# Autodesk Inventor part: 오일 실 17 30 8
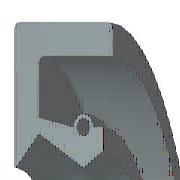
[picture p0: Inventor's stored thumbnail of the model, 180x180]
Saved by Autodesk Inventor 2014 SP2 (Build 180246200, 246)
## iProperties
IsCustomPart: 1
Created: 2012-02
Part Number: 오일 실 17 30 8
Material: 고무
Description: 오일-실
Document SubType Name: Modeling
Standard: KS B 2804
Designer: mduedu
Standards Organization: KS
Language: ko-KR
Size Designation: D - 17 30 8
Categories: <MemberInstance><Categories><Category DisplayName="샤프트 부품" InternalName="7f7aeb1f-a693-4053-b835-cee3144e0d98" Mnemonic="SHFT"><Category DisplayName="실링" Intern
Density: 0.93 g/cm^3
Appearance: 고무 - 검은색 - 버전 1.1
Author: mduedu
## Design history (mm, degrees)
revolve "본체" stored, may be unused: angle "d17" = 90 deg
revolve "스프링1" stored, may be unused: angle "d18" = 90 deg
body "Solid1"
sketch "스케치1"
  geometry: L1 (0, 15)-(8, 15); L2 (8, 13.25)-(1.75, 13.25); L3 (1.75, 10.25)-(4.9, 8.5); L4 (4.9, 8.5)-(0, 8.5); L5 (0, 0)-(9.586, 0) reference; L6 (4.9, 8.5)-(6.3, 9.375); L7 (0, 18)-(0, -3) reference; L8 (-1.941, 0)-(11.507, 0) reference; L9 (4.2, 10.6)-(1.75, 11.21); L10 (1.75, 11.21)-(1.75, 13.25); L11 (0, 15)-(0, 8.588); L12 (4.9, 8.5)-(0, 8.5); L13 (1.75, 10.25)-(0.152, 8.528); L14 (8, 15)-(8, 13.25); L15 (5.6, 10.6)-(6.3, 10.6); L16 (6.3, 10.6)-(6.3, 9.375); C1 r 0.455 at (4.9, 10.6); A1 r 0.7 centre (4.9, 10.6) between (5.6, 10.6) and (4.2, 10.6); A2 r 0.088 centre (0.088, 8.588) between (0, 8.588) and (0.152, 8.528); 1 further point
  constraints: 28 end point, 5 horizontal alignment, 5 point on line, 4 point on circle, 4 vertical alignment, 3 centre point, 3 tangent, 2 collinear, 2 horizontal, 2 perpendicular, 1 coincident, 1 parallel
  dimensions: "d0" = 30 diameter of L1 L5 (= SD2); "d1" = 1.75 distance of L1.end L2.start (= SD); "d2" = 0.91 diameter of C1 (= SPDI); "d3" = 1.4 diameter of A1 (= SPDA); "d4" = 17 diameter of L3.end L5 (= NND); "d5" = 20.5 diameter of L3.start L5 (= TKDM); "d7" = 22.42 diameter of L9.end L5 (= TKDM + 0.24 x SWDT); "d8" = 1.75 distance between parallel lines of L11 L10 (= SD); "d9" = 4.9 distance from line of L11 C1.centre (= SPDST); "d10" = 21.2 diameter of C1.centre L5 (= HLDM); "d11" = 0.0875 radius of A2 (= 0.25 x LAB); "d12" = 6.3 distance between parallel lines of L11 L16 (= SDI); "d13" = 18.75 diameter of L6.end L5 (= ABDM); "d14" = 8 distance from line of L11 L1.end (= SWDT)
fillet "모깎기1" dims "d6" = 0.3 (= RR)
other parameters: "SD2" = 30 [user parameter; used in 1 equation term], "SWDT" = 8 [user parameter; used in 2 equation terms], "RR" = 0.3 [user parameter; used in 1 equation term], "SD" = 1.75 [user parameter; used in 2 equation terms], "NND" = 17 [user parameter; used in 1 equation term], "SPDA" = 1.4 [user parameter; used in 1 equation term], "SPDI" = 0.91 [user parameter; used in 1 equation term], "TKDM" = 20.5 [user parameter; used in 2 equation terms], "HLDM" = 21.2 [user parameter; used in 1 equation term], "ABDM" = 18.75 [user parameter; used in 1 equation term], "SDI" = 6.3 [user parameter; used in 1 equation term], "SPDST" = 4.9 [user parameter; used in 1 equation term], "LAB" = 0.35 [user parameter; used in 1 equation term], "d15" = 0, "d16" = 0, "d19" = 0
